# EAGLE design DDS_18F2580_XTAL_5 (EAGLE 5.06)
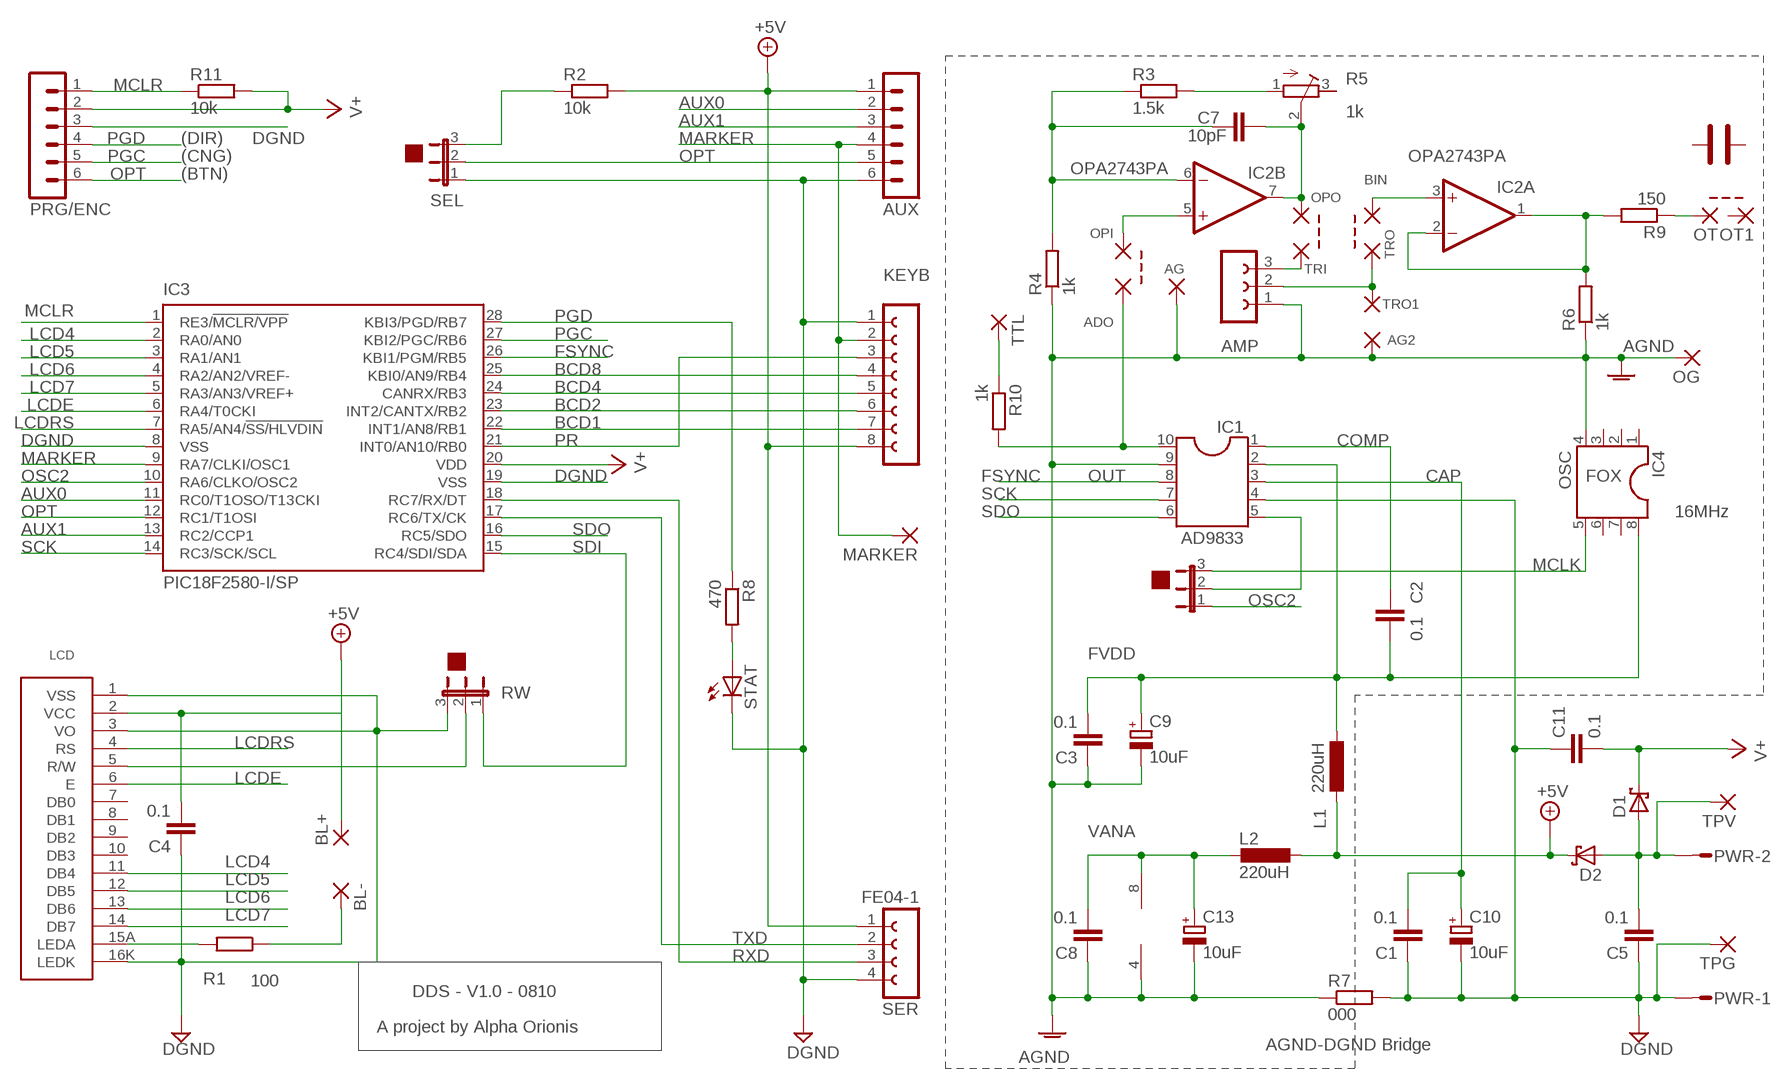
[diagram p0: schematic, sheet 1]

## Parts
ADO  1,6/0,8  [1,6/0,8]
AG  1,6/0,8  [1,6/0,8]
AG2  1,6/0,8  [1,6/0,8]
AMP  FE03-1  [FE03-1]
AUX  MA06-1  [MA06-1]
BIN  1,6/0,8  [1,6/0,8]
BL+  1,6/0,8  [1,6/0,8]
BL-  1,6/0,8  [1,6/0,8]
C1  0.1  C5/3.5  [C5B3.5]
C2  0.1  C5/3.5  [C5B3.5]
C3  0.1  C5/3.5  [C5B3.5]
C4  0.1  C5/3.5  [C5B3.5]
C5  0.1  C5/3.5  [C5B3.5]
C7  10pF  C5/3.5  [C5B3.5]
C8  0.1  C5/3.5  [C5B3.5]
C9  10uF  CPOL-EUTT2D4  [TT2D4]
C10  10uF  CPOL-EUTT2D4  [TT2D4]
C11  0.1  C5/3.5  [C5B3.5]
C13  10uF  CPOL-EUTT2D4  [TT2D4]
CSEL  JP2E  [JP2]
D1  SCHOTTKY-DIODEDO35-7  [DO35-7]
D2  SCHOTTKY-DIODEDO35-7  [DO35-7]
IC1  AD9833  DIL10  [DIL10]
IC2  OPA2743PA  [DIL08]
IC3  PIC18F2580-I/SP  [DIL28-3]
IC4  OSC  DIL8  [DIL08]
KEYB  FE08-1  [FE08]
L1  220uH  L-EU0204/7  [0204/7]
L2  220uH  L-EU0204/7  [0204/7]
LCD  LCD_SIL_16PIN  [SIL16]
MARKER  1,6/0,8  [1,6/0,8]
OG  1,6/0,8  [1,6/0,8]
OPI  1,6/0,8  [1,6/0,8]
OPO  1,6/0,8  [1,6/0,8]
OT  1,6/0,8  [1,6/0,8]
OT1  1,6/0,8  [1,6/0,8]
PRG/ENC  MA06-1  [MA06-1]
PWR  L02P  [L02P]
R1  100  R-EU_0207/7  [0207/7]
R2  10k  R-EU_0207/7  [0207/7]
R3  1.5k  R-EU_0207/7  [0207/7]
R4  1k  R-EU_0207/7  [0207/7]
R5  1k  R-TRIMM64W  [RTRIM64W]
R6  1k  R-EU_0207/7  [0207/7]
R7  000  R-EU_0204/5  [0204/5]
R8  470  R-EU_0207/7  [0207/7]
R9  150  R-EU_0207/7  [0207/7]
R10  1k  R-EU_0207/7  [0207/7]
R11  10k  R-EU_0207/7  [0207/7]
RW  JP2E  [JP2]
SEL  JP2E  [JP2]
SER  FE04-1  [FE04-1]
STAT  LED3MM  [LED3MM]
TPG  1,6/0,8  [1,6/0,8]
TPV  1,6/0,8  [1,6/0,8]
TRI  1,6/0,8  [1,6/0,8]
TRO  1,6/0,8  [1,6/0,8]
TRO1  1,6/0,8  [1,6/0,8]
TTL  1,6/0,8  [1,6/0,8]

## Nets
+5V [pwr]: AUX.1 BL+.1(P) C4.2 D2.C KEYB.8 L1.2 L2.1 LCD.2(VCC) R2.2 SER.1
AGND [gnd]: AG2.1(P) AG.1(P) AMP.1 C3.1 C8.1 C9.- C13.- IC1.9 IC2.4(P:V-) IC4.4 OG.1(P) R4.1 R6.1 R7.1
AUX0: AUX.2 IC3.11(RC0/T1OSO/T13CKI)
AUX1: AUX.3 IC3.13(RC2/CCP1)
BCD1: IC3.22(INT1/AN8/RB1) KEYB.7
BCD2: IC3.23(INT2/CANTX/RB2) KEYB.6
BCD4: IC3.24(CANRX/RB3) KEYB.5
BCD8: IC3.25(KBI0/AN9/RB4) KEYB.4
CAP: C1.2 C10.+ IC1.3
COMP: C2.2 IC1.1
DGND [gnd]: AUX.6 C1.1 C4.1 C5.1 C10.- C11.1 IC1.4 IC3.8(VSS) IC3.19(VSS) KEYB.1 LCD.1(VSS) LCD.3(VO) LCD.16K(LEDK) PRG/ENC.3 PWR.1 R7.2 RW.3 SEL.1 SER.4 STAT.K(C) TPG.1(P)
FSYNC: IC1.8 IC3.26(KBI1/PGM/RB5)
FVDD [pwr]: C2.1 C3.2 C9.+ IC1.2 IC4.8 L1.1
LCD4: IC3.2(RA0/AN0) LCD.11(DB4)
LCD5: IC3.3(RA1/AN1) LCD.12(DB5)
LCD6: IC3.4(RA2/AN2/VREF-) LCD.13(DB6)
LCD7: IC3.5(RA3/AN3/VREF+) LCD.14(DB7)
LCDE: IC3.6(RA4/T0CKI) LCD.6(E)
LCDRS: IC3.7(RA5/AN4/!SS/HLVDIN) LCD.4(RS)
MARKER: AUX.4 IC3.9(RA7/CLKI/OSC1) KEYB.2 MARKER.1(P)
MCLK: CSEL.3 IC4.5
MCLR: IC3.1(RE3/!MCLR/VPP) PRG/ENC.1 R11.1
N$1: R2.1 SEL.3
N$2: CSEL.2 IC1.5
N$3: R8.2 STAT.A
N$4: C5.2 D1.A D2.A PWR.2 TPV.1(P)
N$5: LCD.5(R/W) RW.2
N$6: R10.1 TTL.1(P)
N$7: OT.1(P) R9.1
N$8 [pwr]: BL-.1(P) R1.1
N$21: LCD.15A(LEDA) R1.2
N$29: IC2.5(B:+IN) OPI.1(P)
N$32: AMP.3 TRI.1(P)
N$34: AMP.2 TRO1.1(P) TRO.1(P)
N$35: R3.2 R5.1(E)
N$36: C7.2 IC2.6(B:-IN) R3.1 R4.2
N$37: BIN.1(P) IC2.3(A:+IN)
N$38: IC2.1(A:OUT) IC2.2(A:-IN) R6.2 R9.2
N$39: C7.1 IC2.7(B:OUT) OPO.1(P) R5.2(S)
OPT: AUX.5 IC3.12(RC1/T1OSI) PRG/ENC.6 SEL.2
OSC2: CSEL.1 IC3.10(RA6/CLKO/OSC2)
PGC: IC3.27(KBI2/PGC/RB6) PRG/ENC.5
PGD: IC3.28(KBI3/PGD/RB7) PRG/ENC.4 R8.1
PR: IC3.21(INT0/AN10/RB0) KEYB.3
RXD: IC3.18(RC7/RX/DT) SER.3
SCK: IC1.7 IC3.14(RC3/SCK/SCL)
SDI: IC3.15(RC4/SDI/SDA) RW.1
SDO: IC1.6 IC3.16(RC5/SDO)
TXD: IC3.17(RC6/TX/CK) SER.2
V+: C11.2 D1.C IC3.20(VDD) PRG/ENC.2 R11.2
VANA [pwr]: C8.2 C13.+ IC2.8(P:V+) L2.2
WOUT: ADO.1(P) IC1.10 R10.2
Unconnected: IC4.1 IC4.2 IC4.3 IC4.6 IC4.7 LCD.7(DB0) LCD.8(DB1) LCD.9(DB2) LCD.10(DB3) OT1.1(P) R5.3(A)

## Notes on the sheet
- (DIR)
- (CNG)
- (BTN)
- OUT | FOX
- 16MHz
- MCLK
- DDS - V1.0 - 0810
- A project by Alpha Orionis
- AGND-DGND Bridge

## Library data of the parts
ADO AG AG2 BIN BL+ BL- MARKER OG OPI OPO OT OT1 TPG TPV TRI TRO TRO1 TTL = wirepad:1,6/0,8: THROUGH-HOLE PAD
AMP = con-lsta:FE03-1: FEMALE HEADER
AUX PRG/ENC = con-lstb:MA06-1: PIN HEADER
C1-C5 C7 C8 C11 = capacitor-wima:C: CAPACITOR
C9 C10 C13 = rcl:CPOL-EU: POLARIZED CAPACITOR, European symbol
CSEL RW SEL = jumper:JP2E: JUMPER
D1 D2 = diode:SCHOTTKY-DIODE: Schottky Diode
IC1 = ic-package:DIL10: Dual In Line / Socket
IC2 = linear:OPA2743: 12V, 7MHz, CMOS, Rail-to-Rail I/O Dual OP AMP Source: http://focus.ti.com/lit/ds/sbos201/sbos201.pdf
IC3 = microchip-6:PIC18F2*80: 28-Pin Enhanced Flash Microcontrollers with ECAN(TM) Technology 10-Bit A/D and nanoWatt Technology Source: http://www.microchip.com .. 39637a.pdf
IC4 = ic-package:DIL8: Dual In Line / Socket
KEYB = con-lsta:FE08-1: FEMALE HEADER
L1 L2 = rcl:L-EU: INDUCTOR, European symbol
LCD = lcd_2x16_led_backlight:LCD_SIL_16PIN: 16 pin SIL LCD display (N rows x L characters)
PWR = con-amp-mt:L02P: AMP MT CONNECTOR
R1-R4 R6-R11 = rcl:R-EU_: RESISTOR, European symbol
R5 = resistor:R-TRIMM: Trimm resistor
SER = con-lsta:FE04-1
STAT = led:LED: LED

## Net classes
0 default: width 0.254 mm
1 gnd: width 0.61 mm
2 pwr: width 0.406 mm

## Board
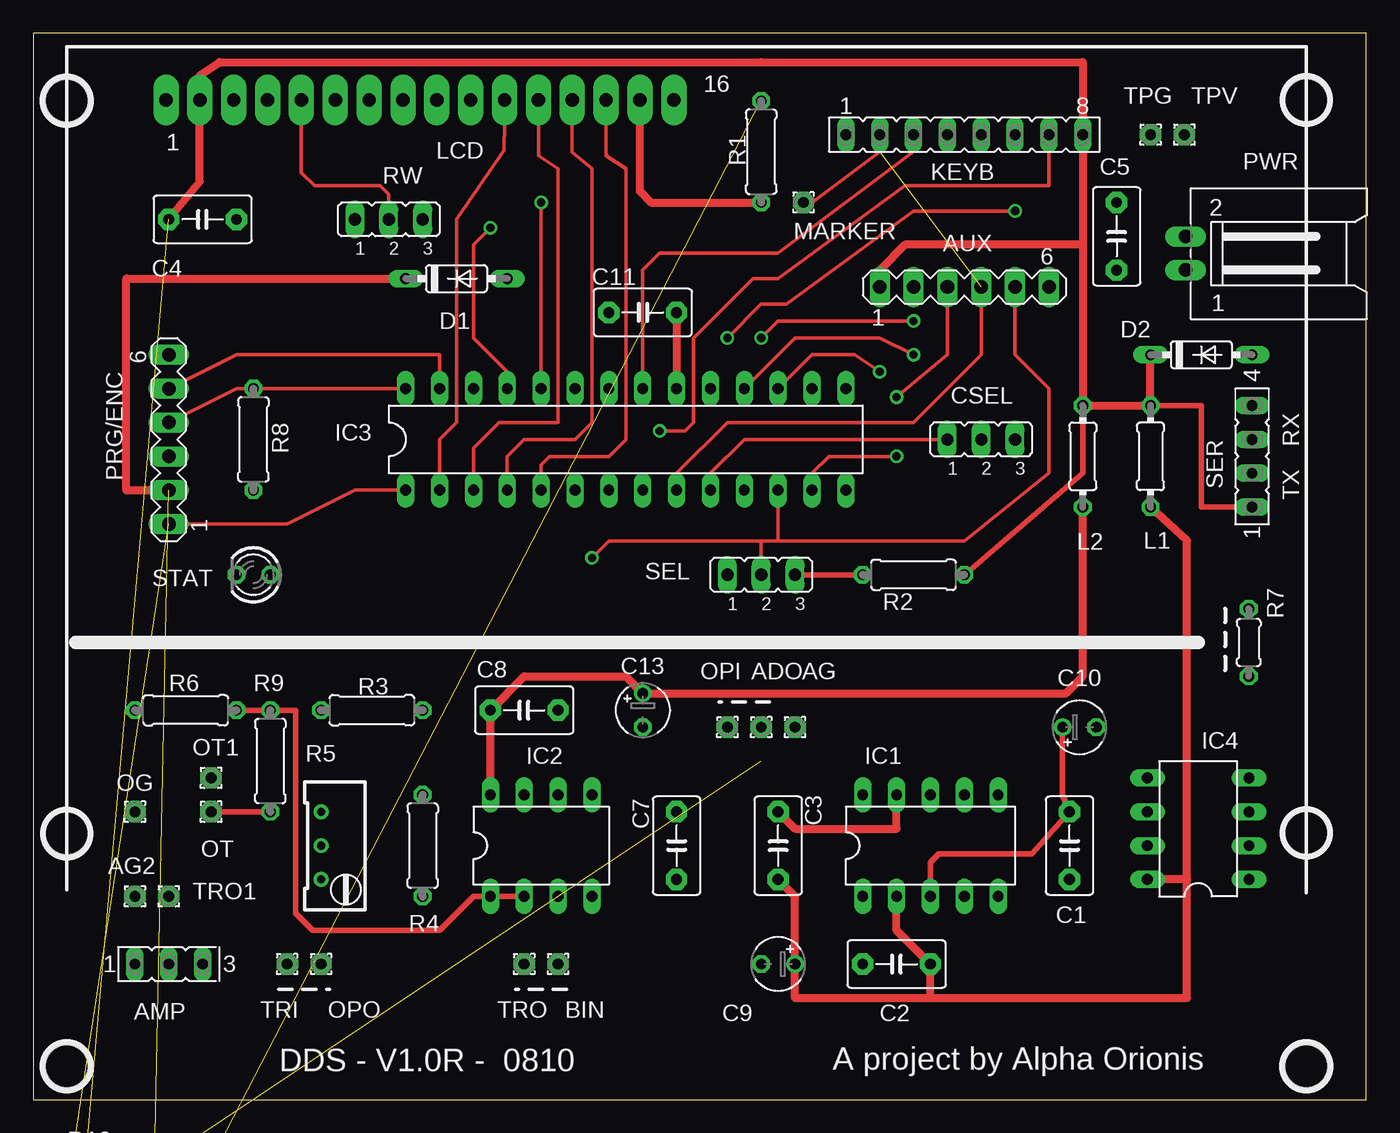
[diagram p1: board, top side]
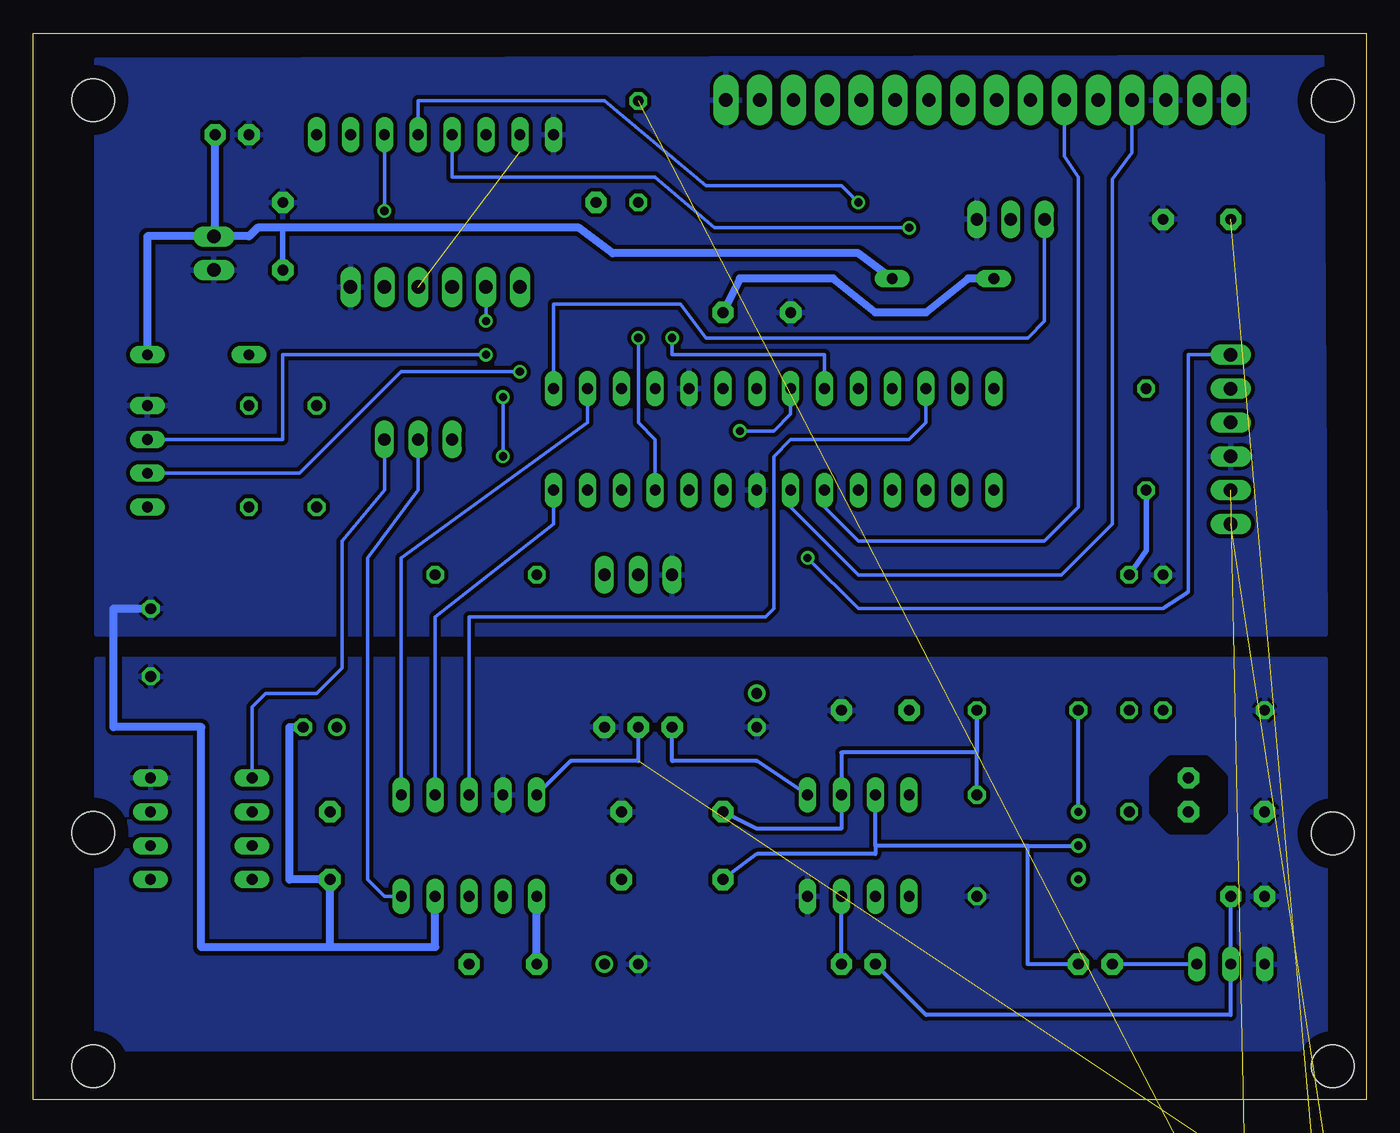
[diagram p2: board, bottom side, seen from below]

Size 100 x 80 mm. Coordinates in mm from the lower left corner, seen from the top.
Outline: 0,0 100,0 100,80 0,80 0,0
Copper layers (1*16): Top 0.035mm / dielectric 1.5mm / Bottom 0.035mm
Design rules "default": minimum track width 10mil, minimum drill 24mil, track to track 8mil, track to pad 8mil, pad to pad 8mil, via to via 8mil, smd to smd 8mil, copper to edge 40mil, drill to drill 8mil, minimum pad ring 10mil, minimum via ring 8mil, stop-mask expansion 4mil, vias tented up to drill 0mil, thermal gap 10mil
Holes 3.2 mm at 2.5,74.96 2.5,19.96 95.5,75 95.5,20 2.5,2.5 95.5,2.5
bRestrict: area 10.8,20.3 to 15.9,25.4

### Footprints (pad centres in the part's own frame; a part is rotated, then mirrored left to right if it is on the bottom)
1,6/0,8 = drill 0.813 pad 1.6 octagon: 1 0,0
FE03-1 = drill 0.813 long: 1 -2.54,0; 2 0,0; 3 2.54,0
MA06-1 = drill 1.016 long: 1 -6.35,0; 2 -3.81,0; 3 -1.27,0; 4 1.27,0; 5 3.81,0; 6 6.35,0
C5B3.5 = drill 0.813 pad 1.6 octagon: 1 -2.54,0; 2 2.54,0
TT2D4 = drill 0.813 round: + -1.27,0 | drill 0.813 octagon: - 1.27,0
JP2 = drill 0.914 long: 1 -2.54,0; 2 0,0; 3 2.54,0
DO35-7 = drill 0.813 long: A 3.81,0; C -3.81,0
DIL10 = drill 0.813 long: 1 -5.08,-3.81; 2 -2.54,-3.81; 3 0,-3.81; 4 2.54,-3.81; 5 5.08,-3.81; 6 5.08,3.81; 7 2.54,3.81; 8 0,3.81; 9 -2.54,3.81; 10 -5.08,3.81
DIL08 = drill 0.813 long: 1 -3.81,-3.81; 2 -1.27,-3.81; 3 1.27,-3.81; 4 3.81,-3.81; 5 3.81,3.81; 6 1.27,3.81; 7 -1.27,3.81; 8 -3.81,3.81
DIL28-3 = drill 0.813 long: 1 -16.51,-3.81; 2 -13.97,-3.81; 3 -11.43,-3.81; 4 -8.89,-3.81; 5 -6.35,-3.81; 6 -3.81,-3.81; 7 -1.27,-3.81; 8 1.27,-3.81; 9 3.81,-3.81; 10 6.35,-3.81; 11 8.89,-3.81; 12 11.43,-3.81; 13 13.97,-3.81; 14 16.51,-3.81; 15 16.51,3.81; 16 13.97,3.81; 17 11.43,3.81; 18 8.89,3.81; 19 6.35,3.81; 20 3.81,3.81; 21 1.27,3.81; 22 -1.27,3.81; 23 -3.81,3.81; 24 -6.35,3.81; 25 -8.89,3.81; 26 -11.43,3.81; 27 -13.97,3.81; 28 -16.51,3.81
FE08 = drill 0.813 long: 1 -8.89,0; 2 -6.35,0; 3 -3.81,0; 4 -1.27,0; 5 1.27,0; 6 3.81,0; 7 6.35,0; 8 8.89,0
0204/7 = drill 0.813 octagon: 1 -3.81,0; 2 3.81,0
SIL16 = drill 1 pad 1.93 long: 1 -20.32,0; 2 -17.78,0; 3 -15.24,0; 4 -12.7,0; 5 -10.16,0; 6 -7.62,0; 7 -5.08,0; 8 -2.54,0; 9 0,0; 10 2.54,0; 11 5.08,0; 12 7.62,0; 13 10.16,0; 14 12.7,0; 15A 15.24,0; 16K 17.78,0
L02P = drill 1.016 long: 1 1.25,-6.25; 2 -1.25,-6.25
0207/7 = drill 0.813 octagon: 1 -3.81,0; 2 3.81,0
RTRIM64W = drill 0.61 round: 1 1.27,-2.54; 2 1.27,0; 3 1.27,2.54
0204/5 = drill 0.813 octagon: 1 -2.54,0; 2 2.54,0
FE04-1 = drill 0.813 long: 1 -3.81,0; 2 -1.27,0; 3 1.27,0; 4 3.81,0
LED3MM = drill 0.813 octagon: A -1.27,0; K 1.27,0

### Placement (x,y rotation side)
ADO  54.61,27.94 0 top
AG  57.15,27.94 0 top
AG2  7.62,15.24 0 top
AMP  10.16,10.16 0 top
AUX  69.85,60.96 0 top
BIN  39.37,10.16 0 top
BL+  not placed on the board
BL-  not placed on the board
C1  77.74,19.05 90 top
C2  64.77,10.16 180 top
C3  55.88,19.05 270 top
C4  12.7,66.04 180 top
C5  81.28,64.77 270 top
C7  48.26,19.05 90 top
C8  36.83,29.21 180 top
C9  55.88,10.16 180 top
C10  78.49,27.94 0 top
C11  45.72,59.05 0 top
C13  45.72,29.21 270 top
CSEL  71.12,49.53 0 top
D1  31.75,61.59 0 top
D2  87.63,55.88 0 top
IC1  67.31,19.05 0 top
IC2  38.1,19.05 0 top
IC3  44.45,49.53 0 top
IC4  87.4,20.32 90 top
KEYB  69.85,72.39 0 top
L1  83.82,48.26 90 top
L2  78.74,48.26 270 top
LCD  30.27,75 0 top
MARKER  57.78,67.31 0 top
OG  7.62,21.59 0 top
OPI  52.07,27.94 0 top
OPO  21.59,10.16 0 top
OT  13.34,21.59 0 top
OT1  13.34,24.13 0 top
PRG/ENC  10.16,49.53 90 top
PWR  92.71,63.5 270 top
R1  54.61,71.12 270 top
R2  66.04,39.37 0 top
R3  25.4,29.21 180 top
R4  29.21,19.05 90 top
R5  22.86,19.05 180 top
R6  11.43,29.21 0 top
R7  91.19,34.29 90 top
R8  16.51,49.53 270 top
R9  17.78,25.4 90 top
R10  not placed on the board
R11  not placed on the board
RW  26.67,66.04 0 top
SEL  54.61,39.37 0 top
SER  91.44,48.26 90 top
STAT  16.51,39.37 180 top
TPG  83.82,72.39 0 top
TPV  86.36,72.39 0 top
TRI  19.05,10.16 0 top
TRO  36.83,10.16 0 top
TRO1  10.16,15.24 0 top
TTL  not placed on the board

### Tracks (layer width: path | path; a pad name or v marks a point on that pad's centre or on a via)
+5V  (1 unrouted)
  Top 0.406: L1.2 87.63,52.07 87.63,44.45 SER.1 | 63.5,62.23 AUX.1 | L2.1 78.74,46.99 R2.2
  Top 0.61: D2.C L1.2 L2.1 78.74,64.14 | 78.74,64.14 KEYB.8 78.74,77.83 54.61,77.83 13.97,77.83 12.49,76.86 LCD.2 12.49,68.87 C4.2 | 78.74,64.14 65.41,64.14 63.5,62.23
AGND
  Top 0.61: C3.1 57.15,20.32 64.77,20.32 IC1.9
  pour Bottom (isolate 0.305): 3.08,33.02 95.25,33.02 95.25,3.81 3.08,3.81
AUX0  (via drill 0.61)
  Top 0.254: v54.61,57.15 55.88,58.42 v66.04,58.42
  Bottom 0.254: IC3.11 53.34,49.53 54.61,50.8 v54.61,57.15 | v66.04,58.42 AUX.2
AUX1  (via drill 0.61)
  Top 0.254: v64.77,48.26 59.69,48.26 58.42,46.99 IC3.13 | v64.77,52.7 68.58,55.88 AUX.3
  Bottom 0.254: v64.77,48.26 v64.77,52.7
BCD1  (via drill 0.61)
  Top 0.254: v46.99,50.16 48.9,50.16 49.53,50.8 49.53,57.15 53.98,61.59 55.88,61.59 65.41,68.58 76.2,68.58 KEYB.7
  Bottom 0.254: IC3.22 43.18,51.44 44.45,50.16 v46.99,50.16
BCD2  (via drill 0.61)
  Top 0.254: v52.07,57.15 54.61,59.69 56.52,59.69 66.04,66.67 v73.66,66.67
  Bottom 0.254: IC3.23 40.64,55.88 52.07,55.88 v52.07,57.15 | v73.66,66.67 KEYB.6
BCD4  (via drill 0.61)
  Top 0.254: IC3.24 v38.1,67.31
  Bottom 0.254: v38.1,67.31 39.37,68.58 49.53,68.58 57.15,74.93 71.12,74.93 KEYB.5
BCD8  (via drill 0.61)
  Top 0.254: IC3.25 35.56,54.61 33.02,57.15 33.02,64.14 v34.29,65.41
  Bottom 0.254: v34.29,65.41 48.9,65.41 53.34,69.22 68.58,69.22 KEYB.4
CAP
  Top 0.406: IC1.3 67.31,17.78 67.94,18.41 74.93,18.41 C1.2 77.22,22.86 C10.+
COMP
  Bottom 0.406: 62.23,13.97 IC1.1
  Bottom 0.61: C2.2 62.23,13.97
DGND
  Bottom 0.61: IC1.4 69.85,11.43 77.74,11.43 | 77.74,11.43 C1.1 80.78,16.51 80.78,27.94 C10.- | R7.2 93.98,36.83 93.98,27.94 87.4,27.94 87.4,11.43 77.74,11.43
  pour Bottom (isolate 0.305): 3.33,78.22 95.25,77.97 95.25,34.92 3.08,34.92
FSYNC
  Bottom 0.254: IC1.8 67.31,36.2 45.09,36.2 44.45,36.83 44.45,48.26 43.18,49.53 34.29,49.53 33.02,50.8 IC3.26
FVDD
  Top 0.61: L1.1 86.55,41.93 86.55,16.51 | 86.55,16.51 86.55,7.62 67.31,7.62 | 86.55,16.51 IC4.8 | C3.2 57.15,15.24 C9.+ 57.15,7.62 67.31,7.62 | 67.31,7.62 C2.1 64.77,12.7 IC1.2
LCD4
  Top 0.254: IC3.2 30.48,49.53 31.75,50.8 31.75,66.04 35.31,71.23 35.35,73.28 LCD.11
LCD5
  Top 0.254: IC3.3 33.02,48.9 34.92,50.8 39.37,50.8 39.37,69.85 37.89,70.83 LCD.12
LCD6
  Top 0.254: IC3.4 35.56,48.26 36.83,49.53 40.64,49.53 41.91,50.8 41.91,69.85 40.43,71.08 LCD.13
LCD7
  Top 0.254: IC3.5 38.1,47.62 38.73,48.26 43.18,48.26 44.45,49.53 44.45,69.85 42.97,70.83 LCD.14
LCDE
  Bottom 0.254: IC3.6 40.64,44.45 38.1,41.91 24.13,41.91 21.59,44.45 21.59,69.22 22.65,70.78 LCD.6
LCDRS
  Bottom 0.254: IC3.7 43.18,44.45 38.1,39.37 22.86,39.37 19.05,43.18 19.05,69.06 17.57,71.04 LCD.4
MARKER  (1 unrouted)
  Top 0.254: IC3.9 48.26,46.99 52.07,50.8 66.04,50.8 71.12,55.88 AUX.4 | MARKER.1 58.42,67.31 63.5,71.12 KEYB.2
MCLK
  Bottom 0.254: CSEL.3 73.66,45.72 76.83,41.91 76.83,32.38 78.74,30.48 82.57,30.48 83.59,29.46 IC4.5
MCLR  (1 unrouted)
  Top 0.254: IC3.1 24.13,45.72 19.05,43.18 PRG/ENC.1
N$1
  Top 0.406: SEL.3 R2.1
N$2
  Bottom 0.254: IC1.5 73.66,15.24 74.93,16.51 74.93,40.64 71.12,45.72 CSEL.2
N$3
  Bottom 0.406: STAT.A 16.51,41.18 R8.2
N$4
  Bottom 0.406: 81.28,65.41 C5.2 | 86.44,64.77 PWR.2
  Bottom 0.61: D2.A 91.44,64.77 87.63,64.77 PWR.2 86.36,64.85 TPV.1 | 86.44,64.77 83.82,64.77 83.19,65.41 81.28,65.41 59.05,65.41 56.52,63.5 38.1,63.5 D1.A
N$5
  Top 0.254: LCD.5 20.11,69.56 21.09,68.58 26.04,68.58 26.67,67.94 RW.2
N$6  (1 unrouted)
N$7
  Top 0.406: OT.1 R9.1
N$8  (1 unrouted)
N$21
  Top 0.61: LCD.15A 45.51,68.16 46.35,67.31 R1.2
N$29
  Bottom 0.305: IC2.5 45.72,25.4 52.07,25.4 OPI.1
N$32
  Bottom 0.305: AMP.3 TRI.1
N$34
  Bottom 0.305: TRO1.1 AMP.2 10.16,6.35 33.02,6.35 TRO.1
N$35
  Bottom 0.305: R5.1 R3.2
N$36
  Bottom 0.305: R4.2 R3.1 29.21,26.04 39.37,26.04 IC2.6 39.37,20.32 45.72,20.32 C7.2
N$37
  Bottom 0.305: BIN.1 IC2.3
N$38
  Top 0.406: IC2.2 IC2.1 33.02,15.24 30.48,12.7 20.95,12.7 19.68,13.97 19.68,29.21 R9.2 R6.2
N$39
  Bottom 0.305: OPO.1 25.4,10.16 25.4,19.05 | 25.4,19.05 R5.2 | 25.4,19.05 36.83,19.05 | C7.1 45.72,18.41 36.83,18.41 36.83,19.05 | 36.83,19.05 IC2.7
OPT  (via drill 0.61)
  Top 0.254: 54.61,41.91 55.88,41.91 | 54.61,41.91 SEL.2 | 55.88,41.91 IC3.12 | AUX.5 73.66,55.88 76.2,53.34 76.2,46.99 69.85,41.91 55.88,41.91 | v41.91,40.64 43.18,41.91 54.61,41.91
  Bottom 0.254: PRG/ENC.6 13.34,55.88 13.34,38.1 15.24,36.83 38.1,36.83 v41.91,40.64
OSC2
  Top 0.254: CSEL.1 53.34,49.53 50.8,46.99 IC3.10
PGC
  Top 0.254: IC3.27 30.48,55.88 15.24,55.88 PRG/ENC.5
PGD
  Top 0.254: PRG/ENC.4 15.24,53.34 R8.1 IC3.28
PR
  Top 0.254: IC3.21 45.72,62.23 46.99,63.5 55.88,63.5 66.04,71.12 KEYB.3
RXD  (via drill 0.61)
  Top 0.254: IC3.18 57.15,57.15 63.5,57.15 v66.04,55.88
  Bottom 0.254: v66.04,55.88 81.28,55.88 81.28,49.53 SER.3
SCK
  Bottom 0.254: IC1.7 69.85,36.2 60.96,43.18 IC3.14
SDI
  Bottom 0.254: IC3.15 60.96,57.15 60.96,59.69 51.44,59.69 49.53,57.15 25.4,57.15 24.13,58.42 RW.1
SDO
  Bottom 0.254: IC3.16 58.42,50.8 72.39,40.64 IC1.6
TXD  (via drill 0.61)
  Top 0.254: IC3.17 58.42,55.88 61.59,55.88 v63.5,54.61
  Bottom 0.254: v63.5,54.61 72.39,54.61 80.01,46.99 SER.2
V+  (1 unrouted)
  Top 0.61: D1.C 6.99,61.59 6.99,45.72 PRG/ENC.2 | C11.2 IC3.20
  Bottom 0.61: C11.2 46.99,61.59 40.01,61.59 36.83,59.05 33.02,59.05 29.84,61.59 D1.C
VANA
  Top 0.61: IC2.8 C8.2 36.83,31.75 44.45,31.75 C13.+ 77.47,30.48 78.74,31.75 L2.2
WOUT  (1 unrouted)
  Bottom 0.305: IC1.10 59.69,25.4 54.61,25.4 ADO.1

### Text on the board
tPlace: 16 | LCD | RX | TX | DDS - V1.0R - 0810 | A project by Alpha Orionis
